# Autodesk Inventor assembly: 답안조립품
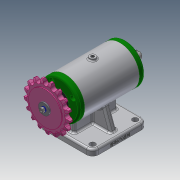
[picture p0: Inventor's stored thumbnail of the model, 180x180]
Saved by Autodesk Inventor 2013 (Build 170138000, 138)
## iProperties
Created: 2019-06
Part Number: 답안조립품
Document SubType Name: Assembly
Designer: user
Author: user
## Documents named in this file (11)
- C:\Users\user\Desktop\490604V1006\답안조립품.iam
- C:\Users\user\Desktop\490604V1006\본체.ipt
- C:\Users\user\Desktop\490604V1006\베어링 6203.ipt
- C:\Users\user\Desktop\490604V1006\볼트 M4.ipt
- C:\Users\user\Desktop\490604V1006\스프로킷.ipt
- C:\Users\user\Desktop\490604V1006\스프링와셔.ipt
- C:\Users\user\Desktop\490604V1006\오일 실 17 30 5.ipt
- C:\Users\user\Desktop\490604V1006\축.ipt
- C:\Users\user\Desktop\490604V1006\커버.ipt
- C:\Users\user\Desktop\490604V1006\키 4x4x12.ipt
- C:\Users\user\Desktop\490604V1006\평와셔.ipt
